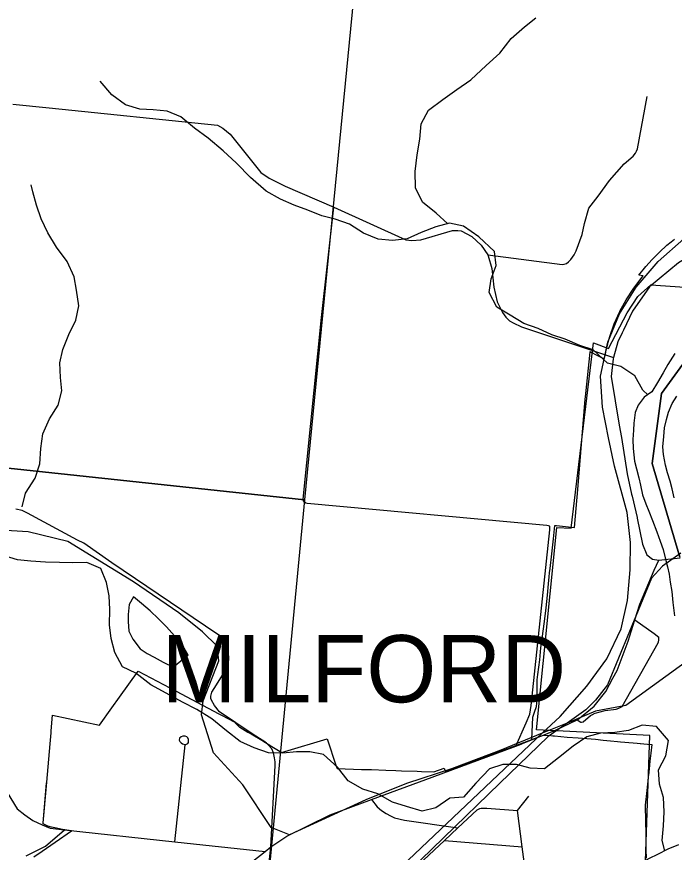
# Model space of a CAD drawing. Extents: x 44.2 to 78.2, y 4.5 to 26.5.
# Drawn here: x 48.145 to 49.072, y 21.309 to 22.487 of the extents above; entities that cross this region are included whole.
import ezdxf

# ---------------------------------------------------------------- set-up
doc = ezdxf.new("R2010")
doc.units = 0
for name, color, linetype in [('GM_X_City_Street', 7, 'Continuous'), ('GM_X_Corporation', 7, 'Continuous'), ('GM_X_Corporation_Text', 7, 'Continuous'), ('GM_X_County_Road', 7, 'Continuous'), ('GM_X_Interstate_Route', 7, 'Continuous'), ('GM_X_Major_River', 7, 'Continuous'), ('GM_X_Minor_Lake', 7, 'Continuous'), ('GM_X_Minor_River', 7, 'Continuous'), ('GM_X_Rail_Line', 7, 'Continuous'), ('GM_X_Section', 7, 'Continuous'), ('GM_X_State_Route', 7, 'Continuous'), ('GM_X_US_Route', 7, 'Continuous'), ('SH_Cut_Line', 7, 'Continuous')]:
    doc.layers.add(name, color=color, linetype=linetype)

msp = doc.modelspace()

# ---------------------------------------------------------------- linework, layer by layer
at = {"layer": 'GM_X_City_Street'}
msp.add_line((48.7484, 21.3259), (48.8579, 21.3167), dxfattribs=at)
for points in [[(48.8092, 22.1509), (48.9139, 22.1376), (48.9169, 22.138), (48.92, 22.139), (48.9232, 22.1411), (48.9265, 22.1446), (48.9311, 22.1508), (48.934, 22.1566), (48.9424, 22.1797), (48.9457, 22.1952), (48.9518, 22.2167), (48.965, 22.2336), (48.9806, 22.2558), (49.0015, 22.2793), (49.0142, 22.2901), (49.0173, 22.2943), (49.019, 22.2972), (49.0201, 22.3003), (49.034, 22.3742)], [(48.8486, 21.4588), (48.8635, 21.4915), (48.8683, 21.5039), (48.8704, 21.5161), (48.8965, 21.7635), (48.8968, 21.7666), (48.8968, 21.7673), (48.8967, 21.7681), (48.8962, 21.7687), (48.8947, 21.7692), (48.8925, 21.7696), (48.5546, 21.8007), (48.5529, 21.8012), (48.551, 21.8026), (48.5497, 21.8045), (48.549, 21.8069), (48.5749, 22.0626), (48.5925, 22.2182)], [(48.5051, 21.4549), (48.5005, 21.4601), (48.4973, 21.4629), (48.495, 21.4647), (48.4789, 21.4751), (48.4312, 21.5071), (48.4242, 21.516), (48.4199, 21.5236), (48.4192, 21.526), (48.4191, 21.529), (48.4203, 21.5347), (48.427, 21.5452), (48.4403, 21.5663), (48.4427, 21.5707), (48.4434, 21.573), (48.4443, 21.5814), (48.4437, 21.5917), (48.4424, 21.5989), (48.4391, 21.6066), (48.4354, 21.6116), (48.4275, 21.617), (48.2796, 21.717), (48.2399, 21.7447), (48.2312, 21.749), (48.1605, 21.7871), (48.153, 21.7907), (48.1443, 21.7927)], [(49.0166, 21.6368), (49.0435, 21.6175), (49.0502, 21.6121)], [(48.9985, 21.5144), (49.0493, 21.6045), (49.0498, 21.6059), (49.0502, 21.6082), (49.0504, 21.6105), (49.0502, 21.6121)], [(47.256, 21.3146), (47.5198, 21.4787), (47.5312, 21.4811), (47.543, 21.4816), (47.8259, 21.4616), (47.834, 21.462), (47.84, 21.4632), (47.8507, 21.4672), (48.0047, 21.5192), (48.0108, 21.5195), (48.0143, 21.5188), (48.0157, 21.5178), (48.0272, 21.5058), (48.0505, 21.4779), (48.098, 21.4309), (48.1128, 21.4158), (48.1269, 21.4021), (48.146, 21.3706), (48.1568, 21.3619), (48.1684, 21.3541), (48.1815, 21.3477), (48.1924, 21.3433), (48.2128, 21.3406)], [(48.935, 21.4958), (48.9404, 21.4926), (48.9415, 21.4924), (48.9433, 21.4928), (48.9439, 21.4931), (48.954, 21.5017), (48.9568, 21.5034), (48.9584, 21.5041), (48.9605, 21.505), (48.9749, 21.5088), (48.9901, 21.5108), (48.9938, 21.5122), (48.9985, 21.5144)], [(48.3681, 21.324), (48.3827, 21.4607), (48.3848, 21.4614), (48.3865, 21.4623), (48.3874, 21.4638), (48.3877, 21.4659), (48.3876, 21.4683), (48.3867, 21.4705), (48.3851, 21.4719), (48.3829, 21.4727), (48.3797, 21.4726), (48.3771, 21.4717), (48.3749, 21.47), (48.3745, 21.4673), (48.3752, 21.4654), (48.377, 21.4634), (48.3789, 21.4622), (48.3827, 21.4611)], [(48.5035, 21.3168), (48.5097, 21.4315), (48.5095, 21.4366), (48.5088, 21.4421), (48.5071, 21.4494), (48.5051, 21.4549)], [(48.6453, 21.3834), (48.6536, 21.3732), (48.6595, 21.3681), (48.6659, 21.3638), (48.672, 21.3606), (48.6778, 21.3577), (48.6918, 21.3544), (48.7672, 21.3435)], [(48.8015, 20.5603), (48.8066, 20.5682), (48.8074, 20.5701), (48.8081, 20.5734), (48.8087, 20.5773), (48.8184, 20.6817), (48.8196, 20.6948), (48.8348, 20.8579), (48.8376, 20.8885), (48.8602, 21.0069), (48.869, 21.0527), (48.8823, 21.1226), (48.8825, 21.1283), (48.8815, 21.1363), (48.8809, 21.1405), (48.8694, 21.2289), (48.8579, 21.3167), (48.8512, 21.3682), (48.8671, 21.3884)], [(48.4764, 21.057), (48.504, 21.0861), (48.5068, 21.0891), (48.5384, 21.1226), (48.5825, 21.1693), (48.5942, 21.1817), (48.6677, 21.2504), (48.7484, 21.3259), (48.7672, 21.3435), (48.7944, 21.3689), (48.7963, 21.3701), (48.7981, 21.3707), (48.8, 21.3712), (48.8023, 21.3715), (48.805, 21.3715), (48.808, 21.3714), (48.8512, 21.3682)], [(48.1587, 21.3041), (48.1858, 21.3176), (48.2128, 21.3406)], [(48.2128, 21.3406), (48.3681, 21.324), (48.4954, 21.3104)], [(48.5003, 21.286), (48.5035, 21.3168)]]:
    msp.add_lwpolyline(points, dxfattribs=at)
at = {"layer": 'GM_X_Corporation'}
for points in [[(49.0309, 21.2832), (49.0377, 21.4736), (48.8779, 21.4815), (48.9068, 21.7666), (48.9266, 21.7659), (48.9582, 22.0272), (48.9793, 22.0192), (49.0058, 22.0695), (49.0209, 22.0922), (49.0391, 22.1086), (49.183, 22.0991)], [(48.1698, 21.3027), (48.1812, 21.3107), (48.1996, 21.3235), (48.1997, 21.3235), (48.2229, 21.3392), (48.2098, 21.3415), (48.2016, 21.343), (48.1944, 21.3445), (48.1894, 21.3462), (48.1854, 21.3477), (48.1827, 21.3491), (48.1827, 21.3505), (48.1877, 21.4079), (48.1925, 21.4619), (48.1938, 21.4773), (48.1941, 21.4801), (48.1961, 21.5026), (48.2622, 21.4881), (48.2795, 21.5125), (48.2904, 21.5279), (48.3164, 21.5642), (48.3523, 21.5455), (48.3703, 21.536), (48.3924, 21.5244), (48.4303, 21.5044), (48.434, 21.5025), (48.4431, 21.4976), (48.4527, 21.4926), (48.4528, 21.4925), (48.4539, 21.4913), (48.4583, 21.4866), (48.459, 21.4859), (48.46, 21.4853), (48.4713, 21.4786), (48.4757, 21.476), (48.4911, 21.4671), (48.5052, 21.4583), (48.5189, 21.4499), (48.5235, 21.4512), (48.5829, 21.4689), (48.5958, 21.4304), (48.5968, 21.4272), (48.6314, 21.426), (48.6454, 21.4256), (48.6655, 21.4249), (48.6799, 21.4244), (48.6876, 21.4241), (48.7098, 21.4233), (48.7157, 21.4231), (48.7333, 21.4226), (48.7476, 21.4278), (48.7495, 21.4224), (48.8715, 21.4682), (48.8877, 21.4743), (48.8981, 21.4735), (48.9011, 21.4733), (48.9034, 21.4731), (48.9212, 21.4716), (48.9367, 21.4703), (48.9609, 21.4684), (48.9717, 21.4673), (48.982, 21.4664), (48.992, 21.4654), (48.9962, 21.465), (49.014, 21.4633), (49.0198, 21.4628), (49.0242, 21.4624), (49.0247, 21.4624), (49.0293, 21.462), (49.0343, 21.4615), (49.0404, 21.461), (49.039, 21.4487), (49.0378, 21.4374), (49.0366, 21.4268), (49.0356, 21.4179), (49.0354, 21.416), (49.0352, 21.4141), (49.0334, 21.3962), (49.0312, 21.3755), (49.031, 21.3738), (49.0314, 21.3545), (49.0318, 21.3336), (49.0322, 21.3126), (49.0324, 21.3011)]]:
    msp.add_lwpolyline(points, dxfattribs=at)
at = {"layer": 'GM_X_County_Road'}
msp.add_line((48.9581, 22.0158), (48.9865, 22.0064), dxfattribs=at)
msp.add_lwpolyline([(48.1399, 22.3633), (48.1913, 22.3579), (48.4282, 22.3336), (48.4361, 22.3296), (48.4462, 22.3211), (48.4897, 22.2671), (48.5013, 22.2589), (48.5239, 22.2479), (48.5925, 22.2182), (48.6938, 22.1723), (48.7022, 22.1714), (48.7147, 22.1719), (48.7594, 22.1852), (48.7672, 22.1854), (48.7719, 22.1846), (48.787, 22.1767), (48.8, 22.1647), (48.8092, 22.1509), (48.81, 22.1497), (48.815, 22.1317), (48.8176, 22.1055), (48.8225, 22.0849), (48.8302, 22.0699), (48.8349, 22.063), (48.8399, 22.0579), (48.8449, 22.0551), (48.8568, 22.0497), (48.9581, 22.0158)], dxfattribs=at)
at = {"layer": 'GM_X_Interstate_Route'}
msp.add_lwpolyline([(48.1698, 21.3027), (48.1812, 21.3107), (48.1996, 21.3235), (48.1997, 21.3235), (48.2229, 21.3392), (48.2098, 21.3415), (48.2016, 21.343), (48.1944, 21.3445), (48.1894, 21.3462), (48.1854, 21.3477), (48.1827, 21.3491), (48.1827, 21.3505), (48.1876, 21.4065), (48.1877, 21.4079), (48.1925, 21.4619), (48.1938, 21.4773), (48.1941, 21.4801), (48.1961, 21.5026), (48.2622, 21.4881), (48.2795, 21.5125), (48.2904, 21.5279), (48.3164, 21.5642), (48.3523, 21.5455), (48.3703, 21.536), (48.3924, 21.5244), (48.4303, 21.5044), (48.434, 21.5025), (48.4431, 21.4976), (48.4527, 21.4926), (48.4528, 21.4925), (48.4539, 21.4913), (48.4583, 21.4866), (48.459, 21.4859), (48.46, 21.4853), (48.4713, 21.4786), (48.4757, 21.476), (48.4911, 21.4671), (48.5052, 21.4583), (48.5189, 21.4499), (48.5235, 21.4512), (48.5829, 21.4689), (48.5958, 21.4304), (48.5968, 21.4272), (48.6314, 21.426), (48.6454, 21.4256), (48.6655, 21.4249), (48.6799, 21.4244), (48.6876, 21.4241), (48.7098, 21.4233), (48.7157, 21.4231), (48.7333, 21.4226), (48.7476, 21.4278), (48.7495, 21.4224), (48.8715, 21.4682), (48.8726, 21.4995), (48.8753, 21.5067), (48.8777, 21.5147), (48.8787, 21.524), (48.879, 21.5314), (48.8789, 21.5444), (48.8789, 21.552), (48.8796, 21.5598), (48.8824, 21.5802), (48.8842, 21.5973), (48.8859, 21.6106), (48.8893, 21.6345), (48.8917, 21.6535), (48.8934, 21.6713), (48.8948, 21.6876), (48.8956, 21.6971), (48.8962, 21.7028), (48.8971, 21.7091), (48.8997, 21.7297), (48.9021, 21.751), (48.9037, 21.7698), (48.906, 21.7696), (48.9315, 21.7668), (48.9364, 21.8203), (48.9467, 21.9475), (48.947, 21.9511), (48.9531, 22.0092), (48.9536, 22.0146), (48.9548, 22.014), (48.9619, 22.0103), (48.9734, 22.0043), (48.975, 22.0114), (48.9755, 22.0138), (48.9762, 22.0171), (48.9783, 22.0254), (48.9789, 22.0278), (48.9811, 22.0358), (48.9873, 22.0539), (48.9953, 22.0712), (48.9954, 22.0714), (49.0045, 22.0876), (49.0149, 22.104), (49.0284, 22.1215), (49.022, 22.1222), (49.0318, 22.1344), (49.0411, 22.1445), (49.0512, 22.1548), (49.0617, 22.1645), (49.0675, 22.1692), (49.0725, 22.1731)], dxfattribs=at)
at = {"layer": 'GM_X_Major_River'}
for points in [[(49.0728, 22.0121), (49.0629, 21.9967), (49.0562, 21.9847), (49.0483, 21.9712), (49.0405, 21.958), (49.0297, 21.9503), (49.0211, 21.939), (49.017, 21.9289), (49.0152, 21.9137), (49.0146, 21.9038), (49.0139, 21.8909), (49.014, 21.8783), (49.0159, 21.8601), (49.0187, 21.8497), (49.0222, 21.8367), (49.0247, 21.8264), (49.0274, 21.813), (49.0321, 21.8), (49.036, 21.79), (49.0414, 21.7766), (49.0475, 21.7605), (49.0522, 21.7475), (49.0565, 21.7356), (49.0593, 21.7242), (49.0624, 21.7112), (49.0648, 21.7009), (49.0665, 21.6898), (49.0685, 21.6764), (49.07, 21.6612), (49.0723, 21.6425)], [(49.0721, 21.8087), (49.069, 21.8213), (49.0662, 21.832), (49.0623, 21.8439), (49.0598, 21.8546), (49.0567, 21.8695), (49.0558, 21.8805), (49.0573, 21.8949), (49.0583, 21.9071), (49.0609, 21.9192), (49.0637, 21.9294), (49.0689, 21.9415), (49.0756, 21.952)], [(49.0778, 21.3195), (49.0632, 21.3134), (49.0482, 21.3061), (49.0367, 21.3006), (49.0248, 21.294), (49.0117, 21.284), (49.002, 21.2736), (48.993, 21.2635), (48.9844, 21.2526), (48.9778, 21.2429), (48.9699, 21.2301)]]:
    msp.add_lwpolyline(points, dxfattribs=at)
at = {"layer": 'GM_X_Minor_Lake'}
msp.add_line((48.3871, 21.5869), (48.3662, 21.5702), dxfattribs=at)
msp.add_lwpolyline([(48.3871, 21.5869), (48.3794, 21.6), (48.3679, 21.6143), (48.3567, 21.6267), (48.3452, 21.6383), (48.3333, 21.6496), (48.3213, 21.6597), (48.3101, 21.669), (48.3038, 21.6585), (48.3024, 21.6441), (48.3026, 21.6343), (48.3034, 21.6206), (48.3089, 21.6094), (48.3193, 21.5959), (48.3294, 21.5892), (48.3391, 21.5841), (48.3519, 21.577), (48.3662, 21.5702)], dxfattribs=at)
at = {"layer": 'GM_X_Minor_River'}
for points in [[(48.7531, 22.1948), (48.7365, 22.2095), (48.7175, 22.2254), (48.7072, 22.2456), (48.7068, 22.2684), (48.7098, 22.292), (48.7133, 22.3141), (48.7152, 22.3358), (48.7258, 22.3548), (48.7457, 22.37), (48.7655, 22.3841), (48.7853, 22.3978), (48.807, 22.4179), (48.8261, 22.4351), (48.8421, 22.4556), (48.8611, 22.4723), (48.8768, 22.4849)], [(49.0347, 21.9539), (49.0277, 21.9603), (49.0167, 21.9804), (48.9969, 21.9938), (48.9778, 21.9983), (48.958, 22.017), (48.9389, 22.0231), (48.9183, 22.0322), (48.8993, 22.0383), (48.8802, 22.0474), (48.86, 22.0543), (48.841, 22.066), (48.8219, 22.0771), (48.8112, 22.098), (48.8139, 22.117), (48.8211, 22.136), (48.8189, 22.1558), (48.7968, 22.1764), (48.775, 22.1912), (48.7552, 22.1954), (48.7362, 22.1904), (48.7156, 22.1825), (48.6958, 22.1737), (48.6752, 22.1714), (48.6546, 22.1729), (48.634, 22.1817), (48.6146, 22.1942), (48.5944, 22.2011), (48.5753, 22.206), (48.5559, 22.214), (48.5364, 22.2209), (48.517, 22.2296), (48.4968, 22.2407), (48.4751, 22.2601), (48.4553, 22.2802), (48.4362, 22.2977), (48.4152, 22.3156), (48.3962, 22.3297), (48.3767, 22.3453), (48.3573, 22.3533), (48.3379, 22.3555), (48.3188, 22.3563), (48.2986, 22.3624), (48.2796, 22.3765), (48.2632, 22.3955)], [(48.1531, 21.796), (48.158, 21.8154), (48.1717, 21.8363), (48.1782, 21.8565), (48.1794, 21.8782), (48.1824, 21.8987), (48.1919, 21.92), (48.2037, 21.9394), (48.2091, 21.9592), (48.2072, 21.9782), (48.2064, 21.9988), (48.2106, 22.0178), (48.219, 22.0387), (48.2289, 22.0589), (48.2331, 22.079), (48.2296, 22.1011), (48.2262, 22.1201), (48.2167, 22.1414), (48.2014, 22.162), (48.1892, 22.1821), (48.1797, 22.2015), (48.1732, 22.2209), (48.1683, 22.2399), (48.166, 22.2498)], [(49.0588, 21.3112), (49.0552, 21.3258), (49.0567, 21.3463), (49.0579, 21.3661), (49.0567, 21.3863), (49.0514, 21.4053), (49.0499, 21.4255), (49.0601, 21.4449), (49.064, 21.4669), (49.0472, 21.4863), (49.0266, 21.4882), (49.0076, 21.481), (48.9885, 21.478), (48.9683, 21.4772), (48.9489, 21.4719), (48.9294, 21.4586), (48.9088, 21.4422), (48.889, 21.4266), (48.8692, 21.4278), (48.8498, 21.4331), (48.8307, 21.4327), (48.8117, 21.427), (48.7926, 21.4064), (48.7751, 21.387), (48.756, 21.3855), (48.7362, 21.3718), (48.7168, 21.3669), (48.6946, 21.3737), (48.6752, 21.3798), (48.6543, 21.3916), (48.6333, 21.3981), (48.6127, 21.4099), (48.5975, 21.4293), (48.578, 21.4471), (48.5586, 21.4509), (48.5395, 21.4509), (48.5205, 21.4487), (48.5003, 21.4494), (48.4801, 21.4563), (48.4603, 21.4654), (48.4412, 21.4802), (48.4202, 21.4974), (48.3993, 21.5103), (48.3791, 21.5206), (48.3562, 21.5335), (48.3345, 21.5453), (48.3135, 21.5616), (48.2945, 21.5704), (48.2838, 21.5906), (48.2785, 21.6103), (48.2762, 21.6298), (48.2766, 21.6511), (48.2758, 21.6705), (48.272, 21.6895), (48.264, 21.7089), (48.2442, 21.7176), (48.2247, 21.7169), (48.2057, 21.7176), (48.1858, 21.718), (48.1656, 21.7195), (48.1466, 21.7214), (48.1252, 21.7279)]]:
    msp.add_lwpolyline(points, dxfattribs=at)
at = {"layer": 'GM_X_Rail_Line'}
msp.add_line((48.921, 21.4912), (48.8861, 21.4769), dxfattribs=at)
for points in [[(48.8861, 21.4769), (48.9114, 21.5006), (48.9488, 21.5431), (48.9771, 21.5818), (48.9971, 21.6239), (49.0061, 21.6639), (49.0098, 21.7073), (49.0105, 21.7456), (49.0057, 21.7878), (48.9877, 21.8532), (48.9792, 21.893), (48.9707, 21.9364), (48.9681, 21.9802), (48.9784, 22.0279), (48.995, 22.0678), (49.0182, 22.1053), (49.0496, 22.1417), (49.0855, 22.1734)], [(49.1242, 22.0518), (49.0543, 21.9557), (49.041, 21.8568), (49.0801, 21.7249)], [(49.0801, 21.7249), (49.041, 21.8568), (49.0543, 21.9557), (49.1242, 22.0518)], [(48.8861, 21.4769), (48.8275, 21.4532), (48.7583, 21.4266), (48.6945, 21.4059), (48.6373, 21.3833), (48.5299, 21.3338), (48.5039, 21.3443), (48.4641, 21.404), (48.4229, 21.4492), (48.406, 21.5027), (48.408, 21.5226), (48.4303, 21.5789), (48.4278, 21.5997), (48.4075, 21.6196), (48.3741, 21.6464), (48.3102, 21.6901), (48.2175, 21.747), (48.1614, 21.7609), (48.0675, 21.7662)], [(49.0811, 21.7307), (49.0556, 21.7121), (49.0399, 21.6956), (48.9779, 21.5453), (48.961, 21.5234), (48.9475, 21.5101), (48.921, 21.4912)], [(49.1167, 21.5979), (49.0036, 21.5162), (48.961, 21.5078), (48.921, 21.4912)], [(48.921, 21.4912), (48.8937, 21.4718), (48.8262, 21.4068), (48.5085, 21.0987), (48.4767, 21.0501), (48.435, 20.6205), (48.4251, 20.6), (48.4085, 20.5927), (48.3659, 20.5713), (48.3107, 20.5323), (48.2854, 20.5214), (48.2509, 20.5274), (48.148, 20.594), (48.052, 20.6243), (48.0069, 20.6071), (47.9343, 20.5508), (47.8347, 20.4578), (47.7876, 20.4184), (47.758, 20.3956), (47.7346, 20.388)], [(47.7346, 20.388), (47.7721, 20.4173), (47.8661, 20.505), (47.9693, 20.6043), (48.0878, 20.7165), (48.2425, 20.8674), (48.6253, 21.2298), (48.8508, 21.4438), (48.8861, 21.4769)]]:
    msp.add_lwpolyline(points, dxfattribs=at)
at = {"layer": 'GM_X_Section'}
for points in [[(47.6368, 22.9304), (48.6514, 22.8354), (48.5512, 21.8058), (47.5395, 21.914)], [(48.5512, 21.8058), (48.4564, 20.8172), (47.4461, 20.9212), (47.5395, 21.914)]]:
    msp.add_lwpolyline(points, close=True, dxfattribs=at)
at = {"layer": 'GM_X_State_Route'}
for points in [[(49.0939, 22.1495), (49.0913, 22.1479), (49.0781, 22.1399), (49.037, 22.106), (49.0134, 22.0714), (49.0005, 22.0448)], [(49.0005, 22.0448), (48.9987, 22.0411), (48.9924, 22.0282), (48.9865, 22.0064), (48.986, 22.0046), (48.983, 21.9796), (48.9942, 21.911), (48.9979, 21.8937), (49.0058, 21.8424), (49.012, 21.8139), (49.0128, 21.8109)], [(49.0128, 21.8109), (49.0181, 21.7889), (49.0197, 21.7808)], [(49.0197, 21.7808), (49.0199, 21.7798), (49.0273, 21.7432), (49.0335, 21.7281), (49.0416, 21.7224), (49.0502, 21.7209)]]:
    msp.add_lwpolyline(points, dxfattribs=at)
at = {"layer": 'GM_X_US_Route'}
msp.add_line((49.0502, 21.7209), (49.0803, 21.7243), dxfattribs=at)
for points in [[(48.9855, 21.5543), (48.9914, 21.5653), (49.0073, 21.6068), (49.0166, 21.6368), (49.0234, 21.6586), (49.0439, 21.7067), (49.0502, 21.7209)], [(48.8583, 21.4625), (48.8945, 21.477), (48.9047, 21.4811), (48.935, 21.4958), (48.9362, 21.4964), (48.959, 21.5151), (48.9755, 21.5356), (48.9855, 21.5543)], [(48.232, 21.1027), (48.2726, 21.1348), (48.3543, 21.1993), (48.4954, 21.3104), (48.5035, 21.3168), (48.5263, 21.3317), (48.5872, 21.362), (48.6453, 21.3834), (48.7309, 21.415), (48.8486, 21.4588), (48.8564, 21.4617), (48.8583, 21.4625)]]:
    msp.add_lwpolyline(points, dxfattribs=at)
at = {"layer": 'SH_Cut_Line'}
for points in [[(49.0801, 21.7249), (49.041, 21.8568), (49.0543, 21.9557), (49.1242, 22.0518)], [(49.1242, 22.0518), (49.0543, 21.9557), (49.041, 21.8568), (49.0801, 21.7249)]]:
    msp.add_lwpolyline(points, dxfattribs=at)

# ---------------------------------------------------------------- texts
at = {"layer": 'GM_X_Corporation_Text'}
msp.add_text('MILFORD', height=0.0947, rotation=0, dxfattribs=at).set_placement((48.3497, 21.5205))

doc.saveas('drawing.dxf')
